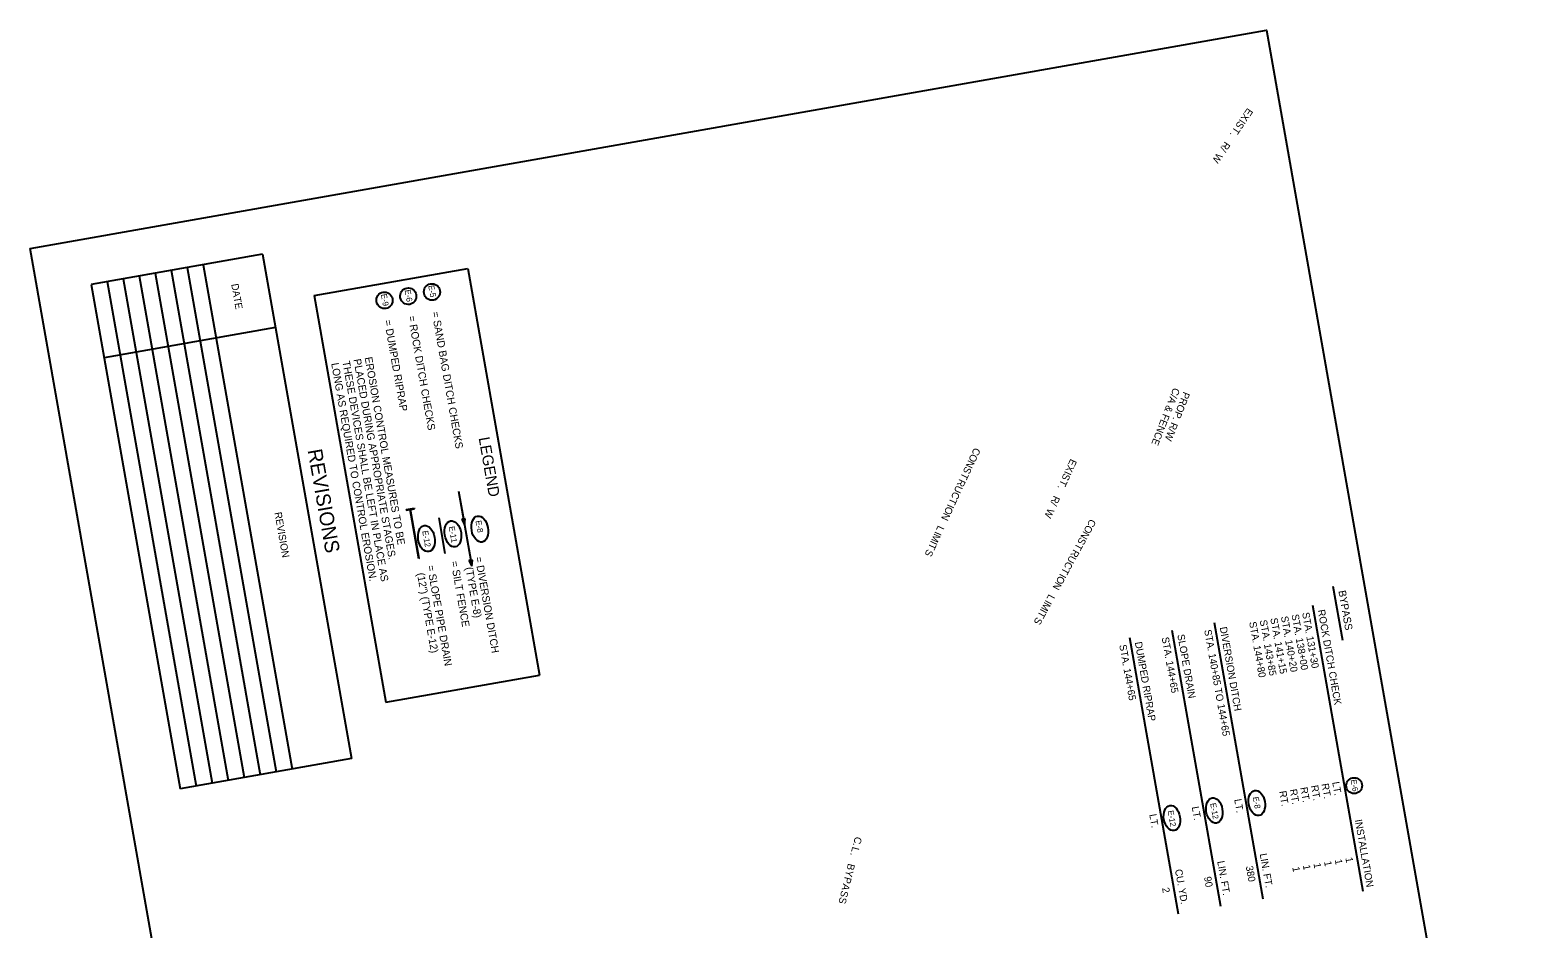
# Model space of a CAD drawing. Extents: x 979945 to 981206, y 1838799 to 1840551.
# Drawn here: x 979945 to 981196, y 1839805 to 1840551 of the extents above; entities that cross this region are included whole.
import ezdxf

# ---------------------------------------------------------------- set-up
doc = ezdxf.new("R2010")
doc.units = 0
for name, color, linetype in [('1', 7, 'Continuous'), ('44', 7, 'Continuous'), ('Default', 7, 'Continuous'), ('G-Border-Sheet', 7, 'Continuous'), ('Level 1', 7, 'Continuous'), ('Level 44', 7, 'Continuous'), ('R_Draft', 7, 'Continuous')]:
    doc.layers.add(name, color=color, linetype=linetype)

msp = doc.modelspace()

# ---------------------------------------------------------------- linework, layer by layer
at = {"layer": '1'}
for p, q in [((980300.1, 1840168.4), (980310.8, 1840108)), ((980305.6, 1840145.6), (980302.8, 1840145.1)), ((980302.8, 1840145.1), (980305, 1840140.6)), ((980303.1, 1840145.2), (980304.5, 1840141.8)), ((980303.5, 1840145.2), (980304.6, 1840141.9)), ((980303.8, 1840145.3), (980304.7, 1840141.9)), ((980304.9, 1840141.9), (980304.6, 1840145.4)), ((980305, 1840141.9), (980304.9, 1840145.5)), ((980305, 1840140.6), (980305.6, 1840145.6)), ((980305.1, 1840141.9), (980305.3, 1840145.5)), ((980311.7, 1840111.3), (980308.8, 1840110.8)), ((980311, 1840107.6), (980310.6, 1840111.1)), ((980311, 1840107.6), (980311, 1840111.2)), ((980311.1, 1840106.3), (980311.7, 1840111.3)), ((980311.1, 1840107.6), (980311.3, 1840111.3)), ((980308.8, 1840110.8), (980311.1, 1840106.3)), ((980309.2, 1840110.9), (980310.6, 1840107.5)), ((980309.5, 1840110.9), (980310.7, 1840107.6)), ((980309.9, 1840111), (980310.8, 1840107.6))]:
    msp.add_line(p, q, dxfattribs=at)
for points in [[(980300.1, 1840168.4), (980305, 1840141)], [(980306.2, 1840134.1), (980310.8, 1840108)]]:
    msp.add_lwpolyline(points, dxfattribs=at)
msp.add_circle((981043.7, 1839924.1), 6.61, dxfattribs=at)
for centre, major_axis, ratio in [((980273.5, 1840129.1), (1.9, -10.8), 0.622952), ((980317.8, 1840137), (1.9, -10.8), 0.622952), ((980927.6, 1839903.5), (1.8, -10.4), 0.638788), ((980962.9, 1839909.7), (1.8, -10.4), 0.638788), ((980892.4, 1839897.2), (1.8, -10.4), 0.638788)]:
    msp.add_ellipse(centre, major_axis=major_axis, ratio=ratio, dxfattribs=at)
at = {"layer": '44'}
for p, q in [((980256.7, 1840153.1), (980263.4, 1840154.3)), ((980256.7, 1840153.1), (980256.8, 1840152.6)), ((980256.8, 1840152.6), (980259.9, 1840153.2)), ((980267.1, 1840112.4), (980259.9, 1840153.2)), ((980260.4, 1840153.2), (980263.5, 1840153.8)), ((980267.6, 1840112.5), (980260.4, 1840153.2)), ((980263.4, 1840154.3), (980263.5, 1840153.8)), ((980267.6, 1840112.5), (980267.1, 1840112.4)), ((981026.1, 1840089.7), (981034, 1840044.8)), ((981009, 1840073.8), (981050.8, 1839836.5)), ((980892.4, 1840053.2), (980932.8, 1839824)), ((980927.6, 1840059.5), (980968, 1839830.2)), ((980857.1, 1840047), (980897.5, 1839817.8))]:
    msp.add_line(p, q, dxfattribs=at)
at = {"layer": 'Default'}
msp.add_lwpolyline([(979944.5, 1840369.9), (980971, 1840550.9), (981196.2, 1839273.6), (981147.4, 1839265), (981177.1, 1839096.8), (981031.8, 1839071.2), (981054, 1838945.6), (980221.5, 1838798.8)], close=True, dxfattribs=at)
at = {"layer": 'G-Border-Sheet'}
for p, q in [((980180.3, 1840330.8), (980308, 1840353.3)), ((980308, 1840353.3), (980367.5, 1840015.8)), ((980180.3, 1840330.8), (980239.8, 1839993.3)), ((980239.8, 1839993.3), (980367.5, 1840015.8))]:
    msp.add_line(p, q, dxfattribs=at)
at = {"layer": 'Level 1'}
for centre, major_axis, ratio in [((980258.4, 1840330.2), (-1.19, 6.78), 0.97521), ((980278.1, 1840333.7), (-1.19, 6.78), 0.97521), ((980238.7, 1840326.8), (-1.19, 6.78), 0.97521), ((980295.5, 1840133), (1.9, -10.8), 0.622952)]:
    msp.add_ellipse(centre, major_axis=major_axis, ratio=ratio, dxfattribs=at)
at = {"layer": 'Level 44'}
msp.add_lwpolyline([(980283.7, 1840146.2), (980288.9, 1840116.6)], dxfattribs=at)
at = {"layer": 'R_Draft'}
for p, q in [((980137.5, 1840365), (979995.2, 1840339.9)), ((980137.5, 1840365), (980211.3, 1839946.5)), ((980048.3, 1840349.3), (980122.1, 1839930.8)), ((980048.3, 1840349.3), (980122.1, 1839930.8)), ((980061.6, 1840351.7), (980135.4, 1839933.1)), ((980074.9, 1840354), (980148.7, 1839935.5)), ((980088.2, 1840356.3), (980162, 1839937.8)), ((979995.2, 1840339.9), (980069, 1839921.4)), ((980008.4, 1840342.3), (980082.2, 1839923.7)), ((980021.7, 1840344.6), (980095.5, 1839926.1)), ((980035, 1840347), (980108.8, 1839928.4)), ((980148.2, 1840304.2), (980005.9, 1840279.1)), ((980211.3, 1839946.5), (980069, 1839921.4))]:
    msp.add_line(p, q, dxfattribs=at)

# ---------------------------------------------------------------- texts
at = {"layer": '1'}
for s, height, p in [('E-8 ', 4.88, (980314.2, 1840143.7)), ('E-12', 4.88, (980270, 1840135.3)), ('E-6 ', 4.8, (981040.8, 1839928.8)), ('E-8', 4.8, (980959.6, 1839914.5)), ('E-12', 4.8, (980888.9, 1839903.1)), ('E-12', 4.8, (980924.2, 1839909.3))]:
    msp.add_text(s, height=height, rotation=280, dxfattribs=at).set_placement(p)
at = {"layer": '44'}
for s, height, p in [('BYPASS', 6.25, (981030.6, 1840085.6)), ('STA. 143+85', 6, (980965.3, 1840061.2)), ('STA. 141+15', 6, (980974.1, 1840062.8)), ('STA. 140+20', 6, (980982.9, 1840064.3)), ('STA. 138+00', 6, (980991.7, 1840065.9)), ('STA. 131+30', 6, (981000.5, 1840067.4)), ('ROCK DITCH CHECK', 6, (981013.5, 1840069.7)), ('SLOPE DRAIN', 6, (980896.9, 1840049.2)), ('STA. 140+85 TO 144+65', 6, (980919.2, 1840053.1)), ('DIVERSION DITCH ', 6, (980932.1, 1840055.4)), ('STA. 144+80', 6, (980956.5, 1840059.7)), ('STA. 144+65', 6, (980848.7, 1840040.7)), ('DUMPED RIPRAP', 6, (980861.6, 1840043)), ('STA. 144+65', 6, (980883.9, 1840046.9)), ('RT.', 6, (981007.8, 1839924)), ('RT.', 6, (981016.6, 1839925.5)), ('LT.', 6, (981025.5, 1839926.9)), ('LT.', 6, (980944.1, 1839912.6)), ('RT.', 6, (980981.4, 1839919.3)), ('RT.', 6, (980990.2, 1839920.8)), ('RT.', 6, (980999, 1839922.4)), ('LT.', 6, (980873.6, 1839900.1)), ('LT.', 6, (980908.9, 1839906.4)), ('INSTALLATION', 6, (981044.2, 1839895.6)), ('LIN. FT.', 6, (980930, 1839861.2)), ('LIN. FT.', 6, (980965.3, 1839867.4)), ('1', 6, (981018.7, 1839861.1)), ('1', 6, (981027.6, 1839862.6)), ('1', 6, (981036.4, 1839864.2)), ('CU. YD.', 6, (980894.9, 1839854.3)), ('90', 6, (980919, 1839848.2)), ('380', 6, (980953.7, 1839857.1)), ('1', 6, (980992.3, 1839856.4)), ('1', 6, (981001.1, 1839858)), ('1', 6, (981009.9, 1839859.5)), ('2', 6, (980884.2, 1839839.1))]:
    msp.add_text(s, height=height, rotation=280, dxfattribs=at).set_placement(p)
at = {"layer": 'Level 1'}
for s, height, p in [('E-5 ', 4.88, (980275, 1840338.9)), ('E-9 ', 4.88, (980235.7, 1840331.7)), ('E-6 ', 4.88, (980255.4, 1840335.2)), ('= ROCK DITCH CHECKS', 6.25, (980258.2, 1840313.4)), ('= SAND BAG DITCH CHECKS', 6.25, (980277.9, 1840316.9)), ('= DUMPED RIPRAP', 6.25, (980238.4, 1840309.9)), ('LONG AS REQUIRED TO CONTROL EROSION.', 6.25, (980194.4, 1840274.4)), ('THESE DEVICES SHALL BE LEFT IN PLACE AS ', 6.25, (980203.7, 1840276)), ('PLACED DURING APPROPRIATE STAGES. ', 6.25, (980212.9, 1840277.7)), ('EROSION CONTROL MEASURES TO BE', 6.25, (980222.2, 1840279.3)), ('E-11 ', 4.88, (980292, 1840138.9)), ('= DIVERSION DITCH', 6.25, (980313.8, 1840113.5)), ('  (12") (TYPE E-12)', 6.25, (980264.8, 1840104.8)), ('= SLOPE PIPE DRAIN', 6.25, (980274, 1840106.4)), ('= SILT FENCE', 6.25, (980293.7, 1840109.9)), ('   (TYPE E-8)', 6.25, (980304.6, 1840111.8))]:
    msp.add_text(s, height=height, rotation=280, dxfattribs=at).set_placement(p)
at = {"layer": 'Level 44'}
msp.add_text('LEGEND', height=9.14, rotation=280, dxfattribs=at).set_placement((980316.8, 1840212.6))
at = {"layer": 'R_Draft'}
for s, height, rotation, p in [('S', 6, 235.8612, (980947.9, 1840476)), ('I', 6, 235.8612, (980949, 1840477.6)), ('X', 6, 235.8612, (980952.2, 1840482.4)), ('E', 6, 235.8612, (980955.2, 1840486.8)), ('.', 6, 235.8612, (980941.4, 1840466.4)), ('T', 6, 235.8612, (980944.7, 1840471.3)), ('/', 6, 235.8612, (980933.2, 1840454.3)), ('R', 6, 235.8612, (980936.4, 1840459)), ('W', 6, 235.8612, (980929.9, 1840449.5)), ('DATE', 6, 280, (980111.4, 1840340.1)), ('C/A & FENCE', 6, 248.4526, (980893.7, 1840254.7)), ('PROP. R/W', 6, 248.4526, (980902, 1840251.4)), ('REVISIONS', 12, 280, (980174.8, 1840202.4)), ('C', 6, 244.4641, (980728.4, 1840205)), ('S', 6, 244.4641, (980721, 1840189.4)), ('N', 6, 244.4641, (980723.4, 1840194.6)), ('O', 6, 244.4641, (980726, 1840199.9)), ('X', 6, 245.3622, (980806.1, 1840190.8)), ('E', 6, 245.3622, (980808.3, 1840195.7)), ('R', 6, 245.3261, (980716, 1840179)), ('T', 6, 244.4641, (980718.6, 1840184.3)), ('T', 6, 245.3622, (980800.5, 1840178.6)), ('S', 6, 245.3622, (980802.9, 1840183.8)), ('I', 6, 245.3622, (980803.7, 1840185.6)), ('T', 6, 245.3261, (980708.8, 1840163.4)), ('C', 6, 245.3261, (980711.2, 1840168.6)), ('U', 6, 245.3261, (980713.6, 1840173.8)), ('R', 6, 245.3622, (980794.3, 1840165.2)), ('.', 6, 245.3622, (980798.1, 1840173.3)), ('REVISION', 6, 280, (980147.3, 1840150.6)), ('N', 6, 245.3261, (980703.1, 1840151)), ('O', 6, 245.3261, (980705.6, 1840156.3)), ('I', 6, 245.3261, (980706.4, 1840158.1)), ('W', 6, 245.3622, (980789.5, 1840154.7)), ('/', 6, 245.3622, (980792, 1840160.1)), ('L', 6, 245.3261, (980698.3, 1840140.4)), ('O', 6, 241.3276, (980821.8, 1840140.9)), ('C', 6, 241.3276, (980824.5, 1840145.8)), ('T', 6, 245.3261, (980691.7, 1840126)), ('I', 6, 245.3261, (980692.5, 1840127.8)), ('M', 6, 245.3261, (980695.2, 1840133.7)), ('I', 6, 245.3261, (980696, 1840135.5)), ('T', 6, 241.3276, (980813.5, 1840125.8)), ('S', 6, 241.3276, (980816.3, 1840130.7)), ('N', 6, 241.3276, (980819, 1840135.7)), ('S', 6, 245.3261, (980689.2, 1840120.7)), ('U', 6, 241.3276, (980808, 1840115.7)), ('R', 6, 241.3276, (980810.7, 1840120.6)), ('I', 6, 241.3276, (980799.7, 1840100.5)), ('T', 6, 241.3276, (980802.5, 1840105.6)), ('C', 6, 241.3276, (980805.2, 1840110.6)), ('N', 6, 241.3276, (980795.9, 1840093.6)), ('O', 6, 241.3276, (980798.8, 1840098.7)), ('M', 6, 241.3276, (980786.8, 1840076.9)), ('I', 6, 241.3276, (980787.8, 1840078.6)), ('L', 6, 241.3276, (980790.3, 1840083.4)), ('S', 6, 241.3276, (980780, 1840064.4)), ('T', 6, 241.3276, (980782.8, 1840069.5)), ('I', 6, 241.3276, (980783.7, 1840071.3)), ('.', 6, 254.9446, (980628, 1839876.7)), ('C', 6, 254.6619, (980629.5, 1839882.2)), ('.', 6, 255.3593, (980625.8, 1839868.6)), ('L', 6, 255.0907, (980627.2, 1839873.8)), ('Y', 6, 256.0873, (980622.2, 1839854.4)), ('B', 6, 255.8046, (980623.6, 1839859.9)), ('S', 6, 256.9496, (980618.1, 1839837.5)), ('A', 6, 256.6575, (980619.4, 1839843.2)), ('P', 6, 256.3748, (980620.8, 1839848.8)), ('S', 6, 257.2324, (980616.8, 1839832))]:
    msp.add_text(s, height=height, rotation=rotation, dxfattribs=at).set_placement(p)

doc.saveas('drawing.dxf')
